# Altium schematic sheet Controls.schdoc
size 297 x 209 mm; Symbol: Drawing-Symbol_A4; @Project Name: Pedal Steel; @Page Count: 2; @Update Date: 2026-10-20; @Create Date: 2026-10-20; @Schematic Name: Schematic1; @Page No: 2; @Page Name: P2; Company: EasyEDA.com; Version: V1.0; Page Size: A4; Device: Drawing-Symbol_A4; @Create Time: 17:31:02; @Update Time: 17:31:02; Border: 1; Width: 1170; Height: 825; Region Start: 1; X Region Count: 6; Y Region Count: 4; Blade Width: 10; Title Block Position: 3
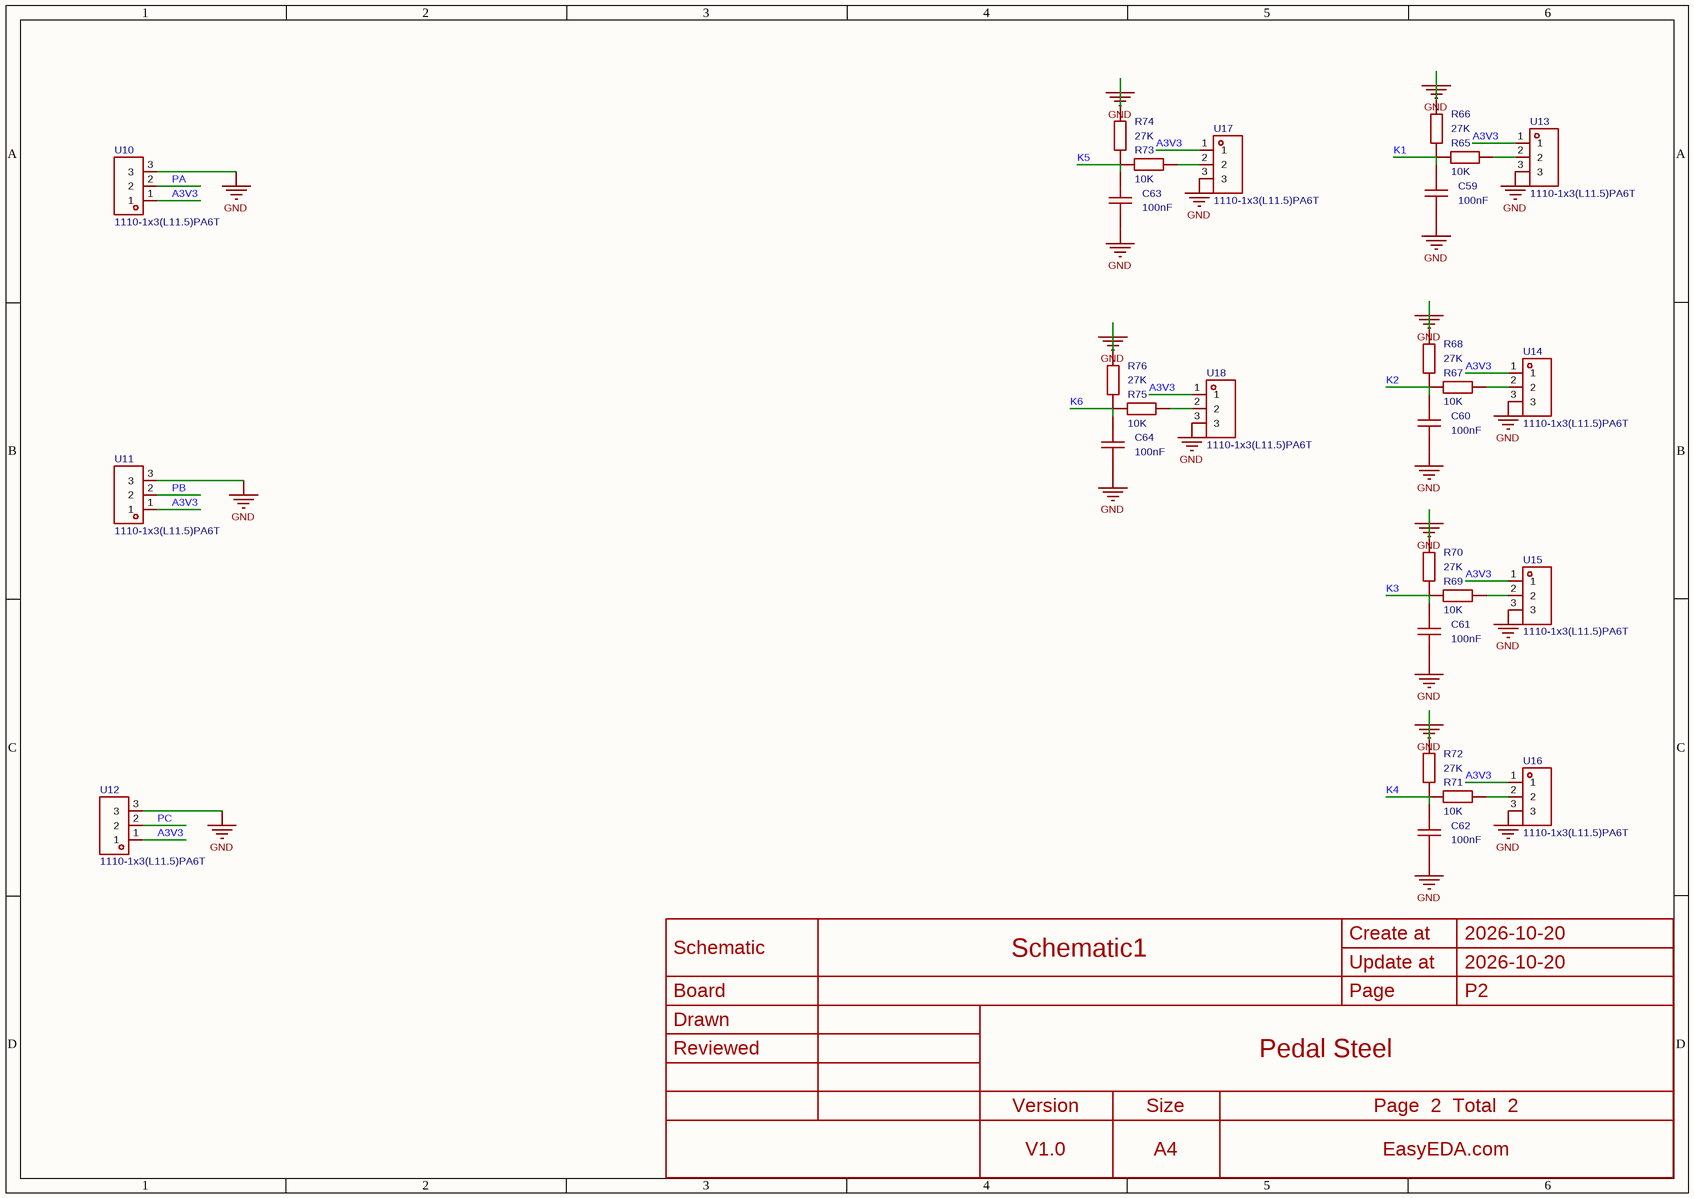
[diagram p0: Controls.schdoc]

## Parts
C59  100nF  [C0603]
C60  100nF  [C0603]
C61  100nF  [C0603]
C62  100nF  [C0603]
C63  100nF  [C0603]
C64  100nF  [C0603]
R65  10K  [R0603]
R66  27K  [R0603]
R67  10K  [R0603]
R68  27K  [R0603]
R69  10K  [R0603]
R70  27K  [R0603]
R71  10K  [R0603]
R72  27K  [R0603]
R73  10K  [R0603]
R74  27K  [R0603]
R75  10K  [R0603]
R76  27K  [R0603]
U10  1110-1x3(L11.5)PA6T  [HDR-TH_3P-P2.54-H-M-W8.0]
U11  1110-1x3(L11.5)PA6T  [HDR-TH_3P-P2.54-H-M-W8.0]
U12  1110-1x3(L11.5)PA6T  [HDR-TH_3P-P2.54-H-M-W8.0]
U13  1110-1x3(L11.5)PA6T  [HDR-TH_3P-P2.54-H-M-W8.0]
U14  1110-1x3(L11.5)PA6T  [HDR-TH_3P-P2.54-H-M-W8.0]
U15  1110-1x3(L11.5)PA6T  [HDR-TH_3P-P2.54-H-M-W8.0]
U16  1110-1x3(L11.5)PA6T  [HDR-TH_3P-P2.54-H-M-W8.0]
U17  1110-1x3(L11.5)PA6T  [HDR-TH_3P-P2.54-H-M-W8.0]
U18  1110-1x3(L11.5)PA6T  [HDR-TH_3P-P2.54-H-M-W8.0]

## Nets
GND: C59.2 C60.2 C61.2 C62.2 C63.2 C64.2 R66.2 R68.2 R70.2 R72.2 R74.2 R76.2 U10.3 U11.3 U12.3 U13.3 U14.3 U15.3 U16.3 U17.3 U18.3
A3V3: U10.1 U11.1 U12.1 U13.1 U14.1 U15.1 U16.1 U17.1 U18.1
K1: C59.1 R65.1 R66.1
K2: C60.1 R67.1 R68.1
K3: C61.1 R69.1 R70.1
K4: C62.1 R71.1 R72.1
K5: C63.1 R73.1 R74.1
K6: C64.1 R75.1 R76.1
PA: U10.2
PB: U11.2
PC: U12.2
NetR65_2: R65.2 U13.2
NetR67_2: R67.2 U14.2
NetR69_2: R69.2 U15.2
NetR71_2: R71.2 U16.2
NetR73_2: R73.2 U17.2
NetR75_2: R75.2 U18.2

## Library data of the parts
C59-C64 = CAP_0603: Symbol: CAP_OLD; ConvertToPcb: yes; ModelId: 624118aa3cc7497086c383c2d72e08520819f05c4eef4c71ace90d822a990e87; ModelName: C0603_L1.6-W0.8-H0.8; ModelTransform: 62.992,31.496,0,0,0,0,0,0,0
R65-R76 = Res_0603: Symbol: Res; ConvertToPcb: yes; ModelId: 112863783b5b41f1b5254f87eedc79320819f05c4eef4c71ace90d822a990e87; ModelTransform: 31.8897,63.7794,0,90,0,0,0,0,0
U10-U18 = 1110-1x3(L11.5)PA6T: Pin Structure:1x3P Pitch:2.54mm Circluar Pins/Square Pins:Pin Header Mounting Type:Right Angle Number of Rows:1 Number of Pins:3P Current Rating:3A Voltage Rating (Max):250V Length of Mating Pin:3.5mm Insulation Height:2.54mm Contact Material:Brass Contac; Manufacturer: CST(永丰盈); AddInBom: yes; ModelId: 8af6a733bb33433f90d20139532c28540819f05c4eef4c71ace90d822a990e87; ModelTransform: 300.3931,314.96,0,0,0,0,0,-143.701,-118.11; Pin Structure: 1x3P; Pitch: 2.54mm; Current Rating: 3A; Voltage Rating (Max): 250V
